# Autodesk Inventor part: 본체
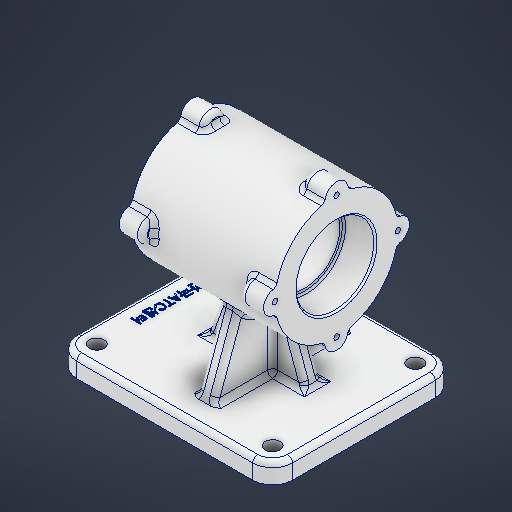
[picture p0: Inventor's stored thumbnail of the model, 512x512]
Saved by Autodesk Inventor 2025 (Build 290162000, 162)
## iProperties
Created: 2025-08
Part Number: 본체
Material: 알루미늄 6061
Document SubType Name: Modeling
Designer: infra006
Density: 2.7 g/cm^3
Appearance: 알루미늄 - 평지
Mass: 1231.61 g
Surface Area: 805.324 cm^2
Volume: 456.153 cm^3
Author: infra006
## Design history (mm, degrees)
sketch "스케치1"
  geometry: L1 (-43.5, 0)-(43.5, 0); L2 (43.5, 0)-(43.5, 23.5); L3 (43.5, 23.5)-(-43.5, 23.5); L4 (-43.5, 23.5)-(-43.5, 0); L5 (-43.5, 0)-(-24.5, 0); L6 (-24.5, 0)-(-24.5, 23.5); L7 (-24.5, 23.5)-(-43.5, 23.5); L8 (-43.5, 23.5)-(-43.5, 0); L9 (43.5, 0)-(24.5, 0); L10 (24.5, 0)-(24.5, 23.5); L11 (24.5, 23.5)-(43.5, 23.5); L12 (43.5, 23.5)-(43.5, 0); L13 (24.5, 0)-(-24.5, 0); L14 (-24.5, 0)-(-24.5, 21); L15 (-24.5, 21)-(24.5, 21); L16 (24.5, 21)-(24.5, 0); L17 (-43.5, 0)-(43.5, 0); L18 (43.5, 0)-(43.5, 37); L19 (43.5, 37)-(-43.5, 37); L20 (-43.5, 37)-(-43.5, 0); 6 further points
  constraints: 40 end point, 10 parallel, 5 horizontal, 5 perpendicular, 2 point on line, 1 coincident, 1 midpoint
  dimensions: "d1" = 87 distance of L3.end L2.end; "d2" = 19 distance of L7.end L6.end; "d3" = 23.5 distance of L6.end L5.end; "d4" = 23.5 distance of L1.end L2.end; "d5" = 19 distance of L10.end L11.end; "d6" = 21 distance of L13.end L14.end; "d7" = 37 distance of L18.end L17.end
revolve "회전1" sketch "스케치1" stored, may be unused: angle "d9" = 90 deg
sketch "스케치2"
  geometry: L1 (0, 0)-(0, -82); L2 (0, -82)-(60, -82); L3 (0, -82)-(-70, -82); L4 (-70, -82)-(-70, -70); L5 (-70, -70)-(60, -70); L6 (60, -70)-(60, -82)
  constraints: 12 end point, 2 horizontal, 2 perpendicular, 2 vertical
  dimensions: "d10" = 82 distance of L1.start L1.end; "d11" = 60 distance of L1.end L2.end; "d12" = 70 distance of L1.end L3.end; "d13" = 12 distance of L3.end L4.end
extrude "돌출1" join sketch "스케치2" stored distance "d14" = 110; taper "d15" = 0 deg
sketch "스케치3"
  geometry: L1 (0, 0)-(0, 110) reference; L2 (0, 0)-(130, 0) reference; L3 (130, 110)-(0, 110) reference; L4 (12, 98)-(118, 98); L5 (118, 98)-(118, 12); L6 (118, 12)-(12, 12); L7 (12, 12)-(12, 98)
  constraints: 8 end point, 2 parallel, 1 horizontal, 1 perpendicular
  dimensions: "d20" = 106 distance between parallel lines of L5 L7; "d21" = 86 distance between parallel lines of L6 L4; "d22" = 12 distance between parallel lines of L1 L7; "d23" = 12 distance between parallel lines of L3 L4
hole "구멍1" sketch "스케치3" at (12, 98), (12, 12), (118, 12), (118, 98) diameter "d24" = 9; stored, may be unused: countersink angle "d28" = 90 deg, drill point angle "d30" = 118 deg; dims "d25" = 6, "d26" = 4, "d27" = 2, "d29" = 12
sketch "스케치4"
  geometry: L1 (65, 50)-(75, 50); L2 (75, 50)-(75, 60); L3 (75, 60)-(65, 60); L4 (65, 60)-(65, 50); L5 (65, 50)-(75, 60); L6 (75, 50)-(65, 60); 1 further point
  constraints: 12 end point, 2 midpoint, 2 parallel, 1 horizontal, 1 perpendicular
  dimensions: "d31" = 10 distance of L3.end L2.end; "d32" = 10 distance of L2.end L1.end
extrude "돌출2" join sketch "스케치4" stored distance "d33" = 110; taper "d34" = 0 deg; dims "d4" = 23.5
sketch "스케치5"
  geometry: L1 (-5, -70)-(-5, -36.661) reference; L2 (-5, -70)-(-30, -70); L3 (-70, -70)-(60, -70) reference; L4 (-30, -70)-(-17.989, -37); L5 (43.5, -37)-(-43.5, -37) reference; L6 (5, -70)-(5, -36.661) reference; L7 (5, -70)-(30, -70); L8 (30, -70)-(17.989, -37); 1 further point
  constraints: 8 end point, 4 point on line
  dimensions: "d35" = 25 distance of L1.start L2.end; "d36" = 70 deg angle of L2 L4; "d37" = 25 distance of L6.start L7.end; "d38" = 70 deg angle of L8 L7; "d124" = 60 distance of L7.end L2.end (derived)
feature "리브1" dims "d39" = 1, "d40" = 10, "d41" = 0, "d42" = 0, "d43" = 1, "d44" = 1
feature "리브2" dims "d45" = 1, "d46" = 10, "d47" = 0, "d48" = 0, "d49" = 1, "d50" = 1
sketch "스케치7"
  geometry: C1 r 7 at (0, 37); C2 r 7 at (-37, 0); C3 r 7 at (0, -37); C4 r 7 at (37, 0); 10 further points
  constraints: 4 centre point, 1 horizontal alignment, 11 other
  dimensions: "d64" = 14 diameter of C1; "d67" = 360 deg dimension on point (0, 0) C1.centre (derived); "d69" = 37 distance of point (0, 0) C1.centre (derived); "d70" = 14 diameter of C2 (derived); "d71" = 37 distance of point (0, 0) C2.centre (derived)
extrude "돌출3" join sketch "스케치7" distance "d72" = 14; taper "d73" = 0 deg
sketch "스케치9"
  geometry: A1 r 37 centre (37, 0) between (0, 0) and (37, 37); 4 further points
  constraints: 4 point on circle, 2 coincident, 1 centre point
  dimensions: "d74" = 74 diameter of A1
hole "구멍3" sketch "스케치9" at (0, 0), (37, 37), (74, 0), (37, -37) diameter "d82" = 3.242; stored, may be unused: countersink angle "d86" = 90 deg, drill point angle "d88" = 118 deg; dims "d83" = 8, "d84" = 4, "d85" = 2, "d87" = 10
chamfer "모따기1" distance "d89" = 1; stored, may be unused: second distance "d90" = 2, angle "d91" = 45 deg
chamfer "모따기2" distance "d92" = 1; stored, may be unused: second distance "d93" = 2, angle "d94" = 45 deg
fillet "모깎기1" dims "d95" = 1
fillet "모깎기2" dims "d96" = 12
fillet "모깎기3" dims "d97" = 3
fillet "모깎기6" dims "d100" = 3
fillet "모깎기7" dims "d101" = 3
sketch "스케치10"
  geometry: L1 (2.821, -29.814)-(2.821, -74.186); L2 (2.821, -74.186)-(-2.821, -74.186); L3 (-2.821, -74.186)-(-2.821, -29.814); L4 (-2.821, -29.814)-(2.821, -29.814); L5 (0, -29.814)-(0, -74.186); L6 (2.821, -52)-(-2.821, -52); L7 (-12, -9)-(-12, -95) reference; L8 (118, -95)-(118, -9) reference; 4 further points
  constraints: 7 midpoint, 4 end point, 1 horizontal alignment, 1 vertical alignment, 2 other
  dimensions: "d103" = 44.37127 distance between parallel lines of L2 L4; "d116" = 118 distance from line of L5 point (118, -52); "d117" = 5.64185 distance between parallel lines of L3 L1
node "작업 평면1"
sketch "스케치12"
  geometry: L1 (-70, -55)-(-70, -41); L2 (-70, -43)-(-70, -52) reference; L3 (-70, -41)-(-26.964, -25.336); A1 r 37 centre (0, 0) between (-35.863, -9.104) and (-9.104, -35.863) reference; 1 further point
  constraints: 4 end point, 1 collinear, 1 point on circle
  dimensions: "d107" = 14 distance of L1.start L1.end; "d108" = 110 deg angle of L1 L3
feature "리브4" sketch "스케치12" dims "d109" = 1, "d110" = 10, "d111" = 0, "d112" = 0, "d113" = 1, "d114" = 1
feature "엠보싱1" dims "d1" = 87, "d2" = 19, "d3" = 23.5, "d4" = 23.5, "d5" = 19, "d6" = 21, "d7" = 37, "d118" = 0.5, "d119" = 0
fillet "모깎기10" dims "d122" = 3
fillet "모깎기11" dims "d123" = 3
node "솔리드1"
mirror "미러2"
mirror "미러3"
mirror "미러4"
mirror "미러5"
node "스케치 - 원형 패턴1" dims "d67" = 360 deg (derived)
feature "A9D066F2-1C7D-4E18-AEED-F7BC21143FA4" dims "d24" = 9, "d25" = 6, "d26" = 4, "d27" = 2, "d28" = 90 deg, "d29" = 12, "d30" = 118 deg
other parameters: "d106" = 5
